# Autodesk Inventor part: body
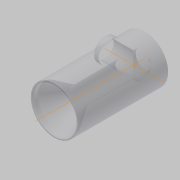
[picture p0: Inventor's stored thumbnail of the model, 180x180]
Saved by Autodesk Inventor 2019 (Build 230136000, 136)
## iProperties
Created: 2000-03
Part Number: body
Project: 9907-000-182
Document SubType Name: Modeling
Designer: Peter Roberts
Density: 2.6 g/cm^3
Material: Glas
Appearance: Glas
Manager: Dave Ford
Company: Autodesk Inc.
Control State: 0
Checked Out: False
Master: False
Shininess: 0.0
Length Units: 11269
Angle Units: 11279
Time Units: 11290
Mass Units: 11284
Length Display Precision: 1
Angle Display Precision: 1
Compacted: True
PropertySet Name: Model Information
Density: 0.0
Volumn: 0.0
Area: 0.0
Title: Valve Body
Subject: Tutorial #3 - part file
Author: Peter Roberts
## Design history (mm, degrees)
node "y-z Plane"
  node "x-z Plane"
  node "x-y Plane"
node "Extrusion1" dims "d0" = 100, "d1" = 0
  sketch "Sketch1"
    geometry: C1 r 26 at (0, 0)
    constraints: 1 centre point
    dimensions: "d16" = 52 diameter of C1
workplane "Work Plane1"
node "Extrusion2" dims "d3" = 76.2, "d4" = 0
node "Revolution1" dims "d5" = 90 deg
  sketch "Sketch4"
    geometry: L1 (-24, 100)-(-24, 94); L2 (-24, 94)-(-10, 73); L3 (-10, 73)-(-10, 0); L4 (0, 66.675)-(0, 44.45); L5 (-24, 100)-(0, 100); L6 (0, 100)-(0, 0) reference; L7 (0, 0)-(-10, 0); L8 (-25.4, 88.9)-(25.4, 88.9) reference
    constraints: 14 end point, 2 parallel, 2 vertical, 1 collinear, 1 perpendicular
    dimensions: "d12" = 24 distance between parallel lines of L1 L6; "d13" = 6 distance from line of L1.end L5; "d14" = 27 distance from line of L2.end L5; "d15" = 10 distance between parallel lines of L3 L6
node "Extrusion3" dims "d6" = 41.75, "d7" = 0
node "Chamfer1" dims "d8" = 0.8, "d9" = 0.8, "d19" = 45 deg
workaxis "Work Axis2"
workaxis "Work Axis3"
node "Volumenkörper1"
node "Volumenkörpern"
node "Oberflächenkörpern"
sketch "Sketch3"
  geometry: L1 (-25.4, 0)-(25.4, 0) reference; L2 (26, 0)-(26, 100) reference; C1 r 12.5 at (0, 12.5)
  constraints: 1 centre point
  dimensions: "d10" = 25 diameter of C1; "d11" = 12.5 distance from line of C1.centre L1; "d18" = 26 distance from line of L2 C1.centre
sketch "Sketch5"
  geometry: C1 r 12.5 at (0, 0) reference; C2 r 10 at (0, 0)
  constraints: 1 centre point, 1 concentric
  dimensions: "d17" = 20 diameter of C2
other parameters: "d2" = -31.75
